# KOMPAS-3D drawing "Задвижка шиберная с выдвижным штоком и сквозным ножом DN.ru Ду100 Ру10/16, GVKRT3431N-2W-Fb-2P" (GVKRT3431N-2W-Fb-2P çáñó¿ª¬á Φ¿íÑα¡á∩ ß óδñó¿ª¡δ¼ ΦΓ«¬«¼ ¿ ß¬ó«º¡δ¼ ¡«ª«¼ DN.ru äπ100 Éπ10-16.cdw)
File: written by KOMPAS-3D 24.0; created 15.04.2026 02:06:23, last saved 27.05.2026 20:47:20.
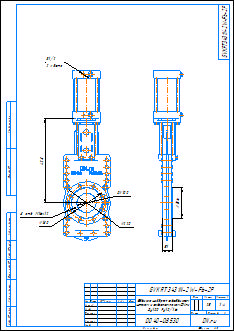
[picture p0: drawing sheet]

Document properties: Автор: DN.ru; Форматы листов документа: A3; Полное имя файла: GVKRT3431N-2W-Fb-2P Задвижка шиберная с выдвижным штоком и сквозным ножом DN.ru Ду100 Ру10-16.m3d; Масса: 25; Наименование: Задвижка шиберная с выдвижным штоком и сквозным ножом DN.ru Ду100 Ру10/16; Количество листов документа: 1; Примечание: D040-08530

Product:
- Part/product: Задвижка шиберная с выдвижным штоком и сквозным ножом DN.ru Ду100 Ру10/16  | designation GVKRT3431N-2W-Fb-2P
    Масса: 25
    Раздел спецификации: Прочие изделия
    Примечание: D040-08530

Views: Вид 1, Вид:1
Referenced files in C:\Работа\GVKRT3431N-2W-Fb-2P Задвижка шиберная со сквозным ножом DN.ru Ду100-250 Ру16\DN100\: GVKRT3431N-2W-Fb-2P Задвижка шиберная со сквозным ножом DN.ru Ду100 Ру16.m3d
Referenced files in C:\Работа\ГОТОВЫЕ ИСХОДНИКИ\GVKRT3431N-2W-Fb-2P Задвижка шиберная со сквозным ножом DN.ru Ду100-250 Ру16\DN100\: GVKRT3431N-2W-Fb-2P Задвижка шиберная с выдвижным штоком и сквозным ножом DN.ru Ду100 Ру10-16.m3d
Referenced files in C:\Program Files\ASCON\KOMPAS-3D v24\Templates\: Чертеж_DN.ru.cdt
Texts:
  GVKRT3431N-2W-Fb-2P
  Чертеж_DN.ru.cdt
  Задвижка шиберная с выдвижным
  штоком и сквозным ножом DN.ru
  Ду100 Ру10/16
  Задвижка шиберная с выдвижным штоком и сквозным ножом DN.ru Ду100 Ру10/16
  GVKRT3431N-2W-Fb-2P Задвижка шиберная с выдвижным штоком и сквозным ножом DN.ru Ду100 Ру10/16
Dimensions and other numbers on the sheet: 0; 3; 2; 4; 428; 8 отв.; 16; 180; 220; 100; 2 места; 1:4; 1; 25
